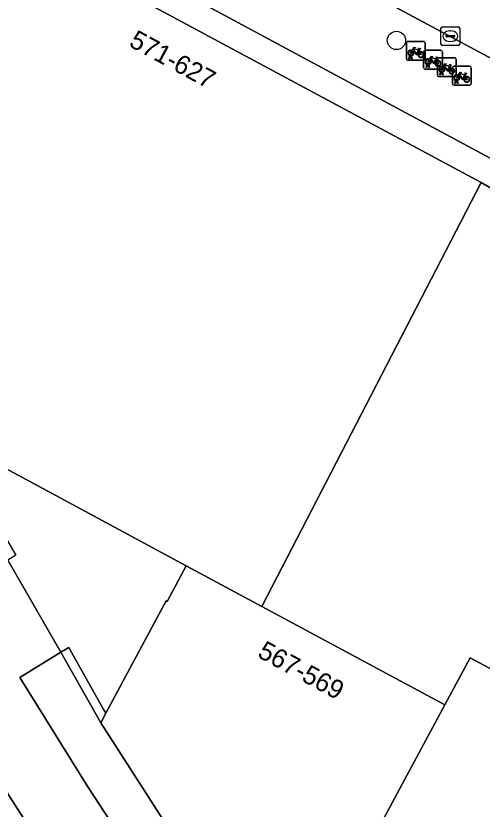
# Model space of a CAD drawing. Extents: x 159489 to 160304, y 383825 to 384531.
# Drawn here: x 159531.94 to 159556.82, y 384258.57 to 384300.92 of the extents above; entities that cross this region are included whole.
import ezdxf

# ---------------------------------------------------------------- set-up
doc = ezdxf.new("R2010")
doc.units = 0
for name, color, linetype in [('IMGEO_Boom', 7, 'Continuous'), ('IMGEO_Erf', 7, 'Continuous'), ('IMGEO_Fietsenrek', 7, 'Continuous'), ('IMGEO_Groenvoorziening', 7, 'Continuous'), ('IMGEO_Kolk', 7, 'Continuous'), ('IMGEO_Pand', 7, 'Continuous'), ('IMGEO_Pand_nummerreeks', 7, 'Continuous'), ('IMGEO_Rijbaan_lokaal_gesloten', 7, 'Continuous'), ('IMGEO_Voetpad_open', 7, 'Continuous')]:
    doc.layers.add(name, color=color, linetype=linetype)

msp = doc.modelspace()

# ---------------------------------------------------------------- linework, layer by layer
at = {"layer": 'IMGEO_Boom'}
msp.add_circle((159552.252, 384299.604), 0.489, dxfattribs=at)
at = {"layer": 'IMGEO_Erf'}
msp.add_lwpolyline([(159631.56, 384209.476), (159640.276, 384225.681), (159611.777, 384241.285), (159616.379, 384249.69), (159600.425, 384258.245), (159593.348, 384245.049), (159582.491, 384250.872), (159578.85, 384252.831), (159587.23, 384268.419), (159590.223, 384274), (159575.933, 384281.657), (159574.935, 384279.809), (159575.127, 384279.7), (159565.449, 384261.675), (159556.176, 384266.653), (159554.827, 384264.14), (159546.454, 384248.546), (159558.913, 384230.144), (159558.499, 384229.864), (159559.363, 384228.538), (159560.934, 384226.137), (159561.341, 384226.407), (159569.144, 384213.675)], dxfattribs=at)
msp.add_lwpolyline([(159541.03, 384271.564), (159528.221, 384278.456), (159531.931, 384272.12), (159531.499, 384271.869), (159534.333, 384266.954), (159534.768, 384267.2), (159536.603, 384263.927), (159536.735, 384263.691), (159539.953, 384269.688), (159540.015, 384269.655)], close=True, dxfattribs=at)
at = {"layer": 'IMGEO_Fietsenrek'}
for p, q in [((159552.854, 384299.547), (159553.695, 384299.547)), ((159553.695, 384299.547), (159552.854, 384299.547)), ((159552.779, 384298.622), (159552.779, 384299.463)), ((159552.779, 384299.463), (159552.779, 384298.622)), ((159553.466, 384299.096), (159553.502, 384299.001)), ((159553.777, 384299.077), (159554.618, 384299.077)), ((159554.618, 384299.077), (159553.777, 384299.077)), ((159553.779, 384299.472), (159553.779, 384298.631)), ((159553.779, 384298.631), (159553.779, 384299.472)), ((159552.906, 384298.631), (159552.945, 384298.791)), ((159552.975, 384298.779), (159552.94, 384298.631)), ((159553.017, 384298.803), (159553.016, 384298.807)), ((159553.058, 384298.631), (159553.024, 384298.773)), ((159553.048, 384298.814), (159553.049, 384298.807)), ((159553.056, 384298.777), (159553.091, 384298.631)), ((159553.702, 384298.152), (159553.702, 384298.993)), ((159553.702, 384298.993), (159553.702, 384298.152)), ((159554.508, 384298.677), (159555.349, 384298.677)), ((159555.349, 384298.677), (159554.508, 384298.677)), ((159554.702, 384299.002), (159554.702, 384298.161)), ((159554.702, 384298.161), (159554.702, 384299.002)), ((159553.704, 384298.547), (159552.863, 384298.547)), ((159552.863, 384298.547), (159553.704, 384298.547)), ((159552.94, 384298.631), (159552.906, 384298.631)), ((159553.091, 384298.631), (159553.058, 384298.631)), ((159553.829, 384298.161), (159553.868, 384298.321)), ((159553.898, 384298.309), (159553.863, 384298.161)), ((159553.94, 384298.333), (159553.939, 384298.337)), ((159553.981, 384298.161), (159553.947, 384298.303)), ((159553.971, 384298.344), (159553.972, 384298.337)), ((159553.979, 384298.307), (159554.014, 384298.161)), ((159554.389, 384298.626), (159554.425, 384298.531)), ((159554.433, 384297.752), (159554.433, 384298.593)), ((159554.433, 384298.593), (159554.433, 384297.752)), ((159555.12, 384298.226), (159555.156, 384298.131)), ((159555.309, 384298.224), (159556.15, 384298.224)), ((159556.15, 384298.224), (159555.309, 384298.224)), ((159555.433, 384298.602), (159555.433, 384297.761)), ((159555.433, 384297.761), (159555.433, 384298.602)), ((159554.627, 384298.077), (159553.786, 384298.077)), ((159553.786, 384298.077), (159554.627, 384298.077)), ((159553.863, 384298.161), (159553.829, 384298.161)), ((159554.014, 384298.161), (159553.981, 384298.161)), ((159554.56, 384297.761), (159554.599, 384297.921)), ((159554.629, 384297.909), (159554.594, 384297.761)), ((159554.671, 384297.933), (159554.67, 384297.937)), ((159554.712, 384297.761), (159554.678, 384297.903)), ((159554.702, 384297.944), (159554.703, 384297.937)), ((159554.71, 384297.907), (159554.745, 384297.761)), ((159555.234, 384297.299), (159555.234, 384298.14)), ((159555.234, 384298.14), (159555.234, 384297.299)), ((159556.234, 384298.149), (159556.234, 384297.308)), ((159556.234, 384297.308), (159556.234, 384298.149)), ((159555.358, 384297.677), (159554.517, 384297.677)), ((159554.517, 384297.677), (159555.358, 384297.677)), ((159554.594, 384297.761), (159554.56, 384297.761)), ((159554.745, 384297.761), (159554.712, 384297.761)), ((159555.361, 384297.308), (159555.4, 384297.468)), ((159555.43, 384297.456), (159555.395, 384297.308)), ((159555.472, 384297.48), (159555.471, 384297.484)), ((159555.513, 384297.308), (159555.479, 384297.45)), ((159555.503, 384297.491), (159555.504, 384297.484)), ((159555.511, 384297.454), (159555.546, 384297.308)), ((159555.921, 384297.773), (159555.957, 384297.678)), ((159556.159, 384297.224), (159555.318, 384297.224)), ((159555.318, 384297.224), (159556.159, 384297.224)), ((159555.395, 384297.308), (159555.361, 384297.308)), ((159555.546, 384297.308), (159555.513, 384297.308))]:
    msp.add_line(p, q, dxfattribs=at)
for points in [[(159553.092, 384299.073), (159553.187, 384299.237), (159553.273, 384299.223), (159553.275, 384299.214), (159553.219, 384299.203), (159553.192, 384299.158), (159553.448, 384299.117)], [(159553.388, 384298.829), (159553.338, 384298.829), (159553.147, 384299.08), (159553.128, 384299.048)], [(159553.435, 384299.092), (159553.178, 384299.133), (159553.161, 384299.104), (159553.328, 384298.884), (159553.435, 384299.092)], [(159553.483, 384298.994), (159553.453, 384299.071), (159553.344, 384298.853), (159553.387, 384298.853)], [(159553.448, 384299.117), (159553.473, 384299.166), (159553.467, 384299.17), (159553.444, 384299.174), (159553.432, 384299.181), (159553.431, 384299.184), (159553.433, 384299.189), (159553.528, 384299.174), (159553.53, 384299.164), (159553.52, 384299.151), (159553.508, 384299.145), (159553.494, 384299.151), (159553.466, 384299.096)], [(159553.113, 384299.021), (159553.061, 384298.931), (159553.021, 384298.906), (159553.022, 384298.953), (159553.077, 384299.047)], [(159553.417, 384298.853), (159553.537, 384298.852), (159553.493, 384298.966)], [(159553.513, 384298.973), (159553.568, 384298.828), (159553.418, 384298.828)], [(159554.015, 384298.603), (159554.11, 384298.767), (159554.196, 384298.753), (159554.198, 384298.744), (159554.142, 384298.733), (159554.115, 384298.688), (159554.371, 384298.647)], [(159554.358, 384298.622), (159554.101, 384298.663), (159554.084, 384298.634), (159554.251, 384298.414), (159554.358, 384298.622)], [(159554.371, 384298.647), (159554.396, 384298.696), (159554.39, 384298.7), (159554.367, 384298.704), (159554.355, 384298.711), (159554.354, 384298.714), (159554.356, 384298.719), (159554.451, 384298.704), (159554.453, 384298.694), (159554.443, 384298.681), (159554.431, 384298.675), (159554.417, 384298.681), (159554.389, 384298.626)], [(159554.036, 384298.551), (159553.984, 384298.461), (159553.944, 384298.436), (159553.945, 384298.483), (159554, 384298.577)], [(159554.311, 384298.359), (159554.261, 384298.359), (159554.07, 384298.61), (159554.051, 384298.578)], [(159554.406, 384298.524), (159554.376, 384298.601), (159554.267, 384298.383), (159554.31, 384298.383)], [(159554.34, 384298.383), (159554.46, 384298.382), (159554.416, 384298.496)], [(159554.436, 384298.503), (159554.491, 384298.358), (159554.341, 384298.358)], [(159554.746, 384298.203), (159554.841, 384298.367), (159554.927, 384298.353), (159554.929, 384298.344), (159554.873, 384298.333), (159554.846, 384298.288), (159555.102, 384298.247)], [(159555.089, 384298.222), (159554.832, 384298.263), (159554.815, 384298.234), (159554.982, 384298.014), (159555.089, 384298.222)], [(159555.102, 384298.247), (159555.127, 384298.296), (159555.121, 384298.3), (159555.098, 384298.304), (159555.086, 384298.311), (159555.085, 384298.314), (159555.087, 384298.319), (159555.182, 384298.304), (159555.184, 384298.294), (159555.174, 384298.281), (159555.162, 384298.275), (159555.148, 384298.281), (159555.12, 384298.226)], [(159554.767, 384298.151), (159554.715, 384298.061), (159554.675, 384298.036), (159554.676, 384298.083), (159554.731, 384298.177)], [(159555.042, 384297.959), (159554.992, 384297.959), (159554.801, 384298.21), (159554.782, 384298.178)], [(159555.137, 384298.124), (159555.107, 384298.201), (159554.998, 384297.983), (159555.041, 384297.983)], [(159555.071, 384297.983), (159555.191, 384297.982), (159555.147, 384298.096)], [(159555.167, 384298.103), (159555.222, 384297.958), (159555.072, 384297.958)], [(159555.547, 384297.75), (159555.642, 384297.914), (159555.728, 384297.9), (159555.73, 384297.891), (159555.674, 384297.88), (159555.647, 384297.835), (159555.903, 384297.794)], [(159555.89, 384297.769), (159555.633, 384297.81), (159555.616, 384297.781), (159555.783, 384297.561), (159555.89, 384297.769)], [(159555.903, 384297.794), (159555.928, 384297.843), (159555.922, 384297.847), (159555.899, 384297.851), (159555.887, 384297.858), (159555.886, 384297.861), (159555.888, 384297.866), (159555.983, 384297.851), (159555.985, 384297.841), (159555.975, 384297.828), (159555.963, 384297.822), (159555.949, 384297.828), (159555.921, 384297.773)], [(159555.568, 384297.698), (159555.516, 384297.608), (159555.476, 384297.583), (159555.477, 384297.63), (159555.532, 384297.724)], [(159555.843, 384297.506), (159555.793, 384297.506), (159555.602, 384297.757), (159555.583, 384297.725)], [(159555.938, 384297.671), (159555.908, 384297.748), (159555.799, 384297.53), (159555.842, 384297.53)], [(159555.872, 384297.53), (159555.992, 384297.529), (159555.948, 384297.643)], [(159555.968, 384297.65), (159556.023, 384297.505), (159555.873, 384297.505)]]:
    msp.add_lwpolyline(points, dxfattribs=at)
for centre, radius, start, end in [((159552.857, 384299.469), 0.0779, 92.4484, 184.2845), ((159552.857, 384299.469), 0.0779, 92.4484, 184.2845), ((159553.701, 384299.469), 0.0779, 2.4484, 94.2845), ((159553.701, 384299.469), 0.0779, 2.4484, 94.2845), ((159553.019, 384298.932), 0.159, 62.6766, 242.1369), ((159553.019, 384298.932), 0.129, 63.3192, 238.903), ((159553.78, 384298.999), 0.0779, 92.4484, 184.2845), ((159553.78, 384298.999), 0.0779, 92.4484, 184.2845), ((159554.624, 384298.999), 0.0779, 2.4484, 94.2845), ((159554.624, 384298.999), 0.0779, 2.4484, 94.2845), ((159552.999, 384298.803), 0.0499, 12.8025, 158.6934), ((159553.019, 384298.932), 0.159, 253.9967, 271.7867), ((159552.999, 384298.803), 0.0174, 12.8025, 163.4502), ((159553.019, 384298.932), 0.129, 253.415, 269.0204), ((159553.019, 384298.932), 0.129, 283.6043, 43.4302), ((159553.019, 384298.932), 0.159, 283.5766, 46.6042), ((159553.546, 384298.848), 0.159, 113.3408, 178.3217), ((159553.546, 384298.848), 0.159, 187.0065, 105.7708), ((159553.546, 384298.848), 0.129, 113.923, 177.9556), ((159553.546, 384298.848), 0.129, 188.6715, 104.5883), ((159554.511, 384298.599), 0.0779, 92.4484, 184.2845), ((159554.511, 384298.599), 0.0779, 92.4484, 184.2845), ((159555.355, 384298.599), 0.0779, 2.4484, 94.2845), ((159555.355, 384298.599), 0.0779, 2.4484, 94.2845), ((159552.857, 384298.625), 0.0779, 182.4484, 274.2845), ((159552.857, 384298.625), 0.0779, 182.4484, 274.2845), ((159553.701, 384298.625), 0.0779, 272.4484, 4.2845), ((159553.701, 384298.625), 0.0779, 272.4484, 4.2845), ((159553.942, 384298.462), 0.159, 62.6766, 242.1369), ((159553.942, 384298.462), 0.129, 63.3192, 238.903), ((159553.922, 384298.333), 0.0499, 12.8025, 158.6934), ((159553.942, 384298.462), 0.159, 253.9967, 271.7867), ((159553.922, 384298.333), 0.0174, 12.8025, 163.4502), ((159553.942, 384298.462), 0.129, 253.415, 269.0204), ((159553.942, 384298.462), 0.129, 283.6043, 43.4302), ((159553.942, 384298.462), 0.159, 283.5766, 46.6042), ((159554.469, 384298.378), 0.159, 113.3408, 178.3217), ((159554.469, 384298.378), 0.159, 187.0065, 105.7708), ((159554.469, 384298.378), 0.129, 113.923, 177.9556), ((159554.469, 384298.378), 0.129, 188.6715, 104.5883), ((159554.673, 384298.062), 0.159, 62.6766, 242.1369), ((159555.312, 384298.146), 0.0779, 92.4484, 184.2845), ((159555.312, 384298.146), 0.0779, 92.4484, 184.2845), ((159556.156, 384298.146), 0.0779, 2.4484, 94.2845), ((159556.156, 384298.146), 0.0779, 2.4484, 94.2845), ((159553.78, 384298.155), 0.0779, 182.4484, 274.2845), ((159553.78, 384298.155), 0.0779, 182.4484, 274.2845), ((159554.673, 384298.062), 0.129, 63.3192, 238.903), ((159554.653, 384297.933), 0.0499, 12.8025, 158.6934), ((159554.624, 384298.155), 0.0779, 272.4484, 4.2845), ((159554.624, 384298.155), 0.0779, 272.4484, 4.2845), ((159554.673, 384298.062), 0.159, 253.9967, 271.7867), ((159554.653, 384297.933), 0.0174, 12.8025, 163.4502), ((159554.673, 384298.062), 0.129, 253.415, 269.0204), ((159554.673, 384298.062), 0.129, 283.6043, 43.4302), ((159554.673, 384298.062), 0.159, 283.5766, 46.6042), ((159555.2, 384297.978), 0.159, 113.3408, 178.3217), ((159555.2, 384297.978), 0.159, 187.0065, 105.7708), ((159555.2, 384297.978), 0.129, 113.923, 177.9556), ((159555.2, 384297.978), 0.129, 188.6715, 104.5883), ((159554.511, 384297.755), 0.0779, 182.4484, 274.2845), ((159554.511, 384297.755), 0.0779, 182.4484, 274.2845), ((159555.474, 384297.609), 0.159, 62.6766, 242.1369), ((159555.474, 384297.609), 0.129, 63.3192, 238.903), ((159555.355, 384297.755), 0.0779, 272.4484, 4.2845), ((159555.355, 384297.755), 0.0779, 272.4484, 4.2845), ((159555.454, 384297.48), 0.0499, 12.8025, 158.6934), ((159555.474, 384297.609), 0.159, 253.9967, 271.7867), ((159555.454, 384297.48), 0.0174, 12.8025, 163.4502), ((159555.474, 384297.609), 0.129, 253.415, 269.0204), ((159555.474, 384297.609), 0.129, 283.6043, 43.4302), ((159555.474, 384297.609), 0.159, 283.5766, 46.6042), ((159556.001, 384297.525), 0.159, 113.3408, 178.3217), ((159556.001, 384297.525), 0.159, 187.0065, 105.7708), ((159556.001, 384297.525), 0.129, 113.923, 177.9556), ((159556.001, 384297.525), 0.129, 188.6715, 104.5883), ((159555.312, 384297.302), 0.0779, 182.4484, 274.2845), ((159555.312, 384297.302), 0.0779, 182.4484, 274.2845), ((159556.156, 384297.302), 0.0779, 272.4484, 4.2845), ((159556.156, 384297.302), 0.0779, 272.4484, 4.2845)]:
    msp.add_arc(centre, radius, start, end, dxfattribs=at)
at = {"layer": 'IMGEO_Groenvoorziening'}
for points in [[(159546.189, 384248.053), (159536.462, 384263.182), (159534.333, 384266.954), (159532.141, 384265.589), (159535.783, 384259.763), (159537.922, 384256.46), (159543.06, 384248.654), (159556.437, 384228.499), (159558.499, 384229.864)], [(159534.333, 384266.954), (159536.462, 384263.182), (159536.735, 384263.691), (159536.603, 384263.927), (159534.768, 384267.2)], [(159531.17, 384259.924), (159529.475, 384258.882), (159530.676, 384256.993), (159531.995, 384254.871), (159533.67, 384255.984), (159532.339, 384258.083)]]:
    msp.add_lwpolyline(points, close=True, dxfattribs=at)
at = {"layer": 'IMGEO_Kolk'}
for p, q in [((159554.701, 384300.333), (159555.553, 384300.333)), ((159554.626, 384299.407), (159554.626, 384300.259)), ((159555.114, 384300.113), (159555.139, 384300.113)), ((159555.627, 384300.259), (159555.627, 384299.407)), ((159554.885, 384299.827), (159554.885, 384299.839)), ((159555.323, 384299.79), (159554.925, 384299.79)), ((159554.928, 384299.876), (159555.326, 384299.876)), ((159555.137, 384299.553), (159555.112, 384299.553)), ((159555.369, 384299.839), (159555.369, 384299.827)), ((159555.553, 384299.333), (159554.701, 384299.333))]:
    msp.add_line(p, q, dxfattribs=at)
for points in [[(159554.701, 384300.333), (159555.553, 384300.333)], [(159554.626, 384299.407), (159554.626, 384300.259)], [(159555.627, 384300.259), (159555.627, 384299.407)], [(159555.553, 384299.333), (159554.701, 384299.333)]]:
    msp.add_lwpolyline(points, dxfattribs=at)
for centre, radius, start, end in [((159554.703, 384300.257), 0.0765, 91.552, 178.448), ((159554.703, 384300.257), 0.0765, 91.552, 178.448), ((159555.551, 384300.257), 0.0765, 1.552, 88.448), ((159555.551, 384300.257), 0.0765, 1.552, 88.448), ((159554.925, 384299.836), 0.0403, 85.8775, 175.7526), ((159554.922, 384299.826), 0.0366, 178.938, 274.7102), ((159555.326, 384299.833), 0.043, 264.8664, 352.4533), ((159555.33, 384299.838), 0.0386, 1.7309, 96.639), ((159554.703, 384299.409), 0.0765, 181.552, 268.448), ((159554.703, 384299.409), 0.0765, 181.552, 268.448), ((159555.551, 384299.409), 0.0765, 271.552, 358.448), ((159555.551, 384299.409), 0.0765, 271.552, 358.448)]:
    msp.add_arc(centre, radius, start, end, dxfattribs=at)
for centre, major_axis, ratio, start_param, end_param in [((159555.113, 384299.833), (-0.387, 0.002), 0.722429, 4.712389, 7.853982), ((159555.138, 384299.833), (-0.39, 0.002), 0.717154, 1.570796, 4.712389)]:
    msp.add_ellipse(centre, major_axis=major_axis, ratio=ratio, start_param=start_param, end_param=end_param, dxfattribs=at)
at = {"layer": 'IMGEO_Pand'}
for points in [[(159556.766, 384292.015), (159527.484, 384307.756), (159519.695, 384293.297), (159519.377, 384292.707), (159522.438, 384287.447), (159523.926, 384284.889), (159527.419, 384278.887), (159528.221, 384278.456), (159541.03, 384271.564), (159545.068, 384269.391)], [(159575.127, 384279.7), (159574.935, 384279.809), (159575.933, 384281.657), (159563.611, 384288.299), (159557.204, 384291.777), (159556.766, 384292.015), (159545.068, 384269.391), (159554.827, 384264.14), (159556.176, 384266.653), (159565.449, 384261.675)], [(159554.827, 384264.14), (159545.068, 384269.391), (159541.03, 384271.564), (159540.015, 384269.655), (159539.953, 384269.688), (159536.735, 384263.691), (159536.462, 384263.182), (159546.189, 384248.053), (159546.454, 384248.546)]]:
    msp.add_lwpolyline(points, close=True, dxfattribs=at)
at = {"layer": 'IMGEO_Rijbaan_lokaal_gesloten'}
msp.add_lwpolyline([(159524.477, 384316.223), (159526.867, 384315.023), (159527.963, 384314.433), (159535.565, 384310.345), (159536.44, 384311.971), (159549.851, 384304.759), (159550.324, 384304.504), (159549.449, 384302.878), (159558.914, 384297.788), (159559.789, 384299.414), (159596.815, 384279.502), (159606.884, 384274.087), (159606.009, 384272.461), (159610.125, 384270.247), (159610.999, 384271.873), (159634.42, 384259.278), (159633.545, 384257.652), (159643.266, 384252.424), (159644.14, 384254.05), (159648.99, 384251.442), (159648.115, 384249.816), (159649.108, 384249.282), (159652.612, 384247.398)], dxfattribs=at)
at = {"layer": 'IMGEO_Voetpad_open'}
for points in [[(159652.612, 384247.398), (159649.108, 384249.282), (159648.115, 384249.816), (159643.266, 384252.424), (159633.545, 384257.652), (159610.125, 384270.247), (159606.009, 384272.461), (159595.94, 384277.876), (159558.914, 384297.788), (159549.449, 384302.878), (159535.565, 384310.345), (159527.963, 384314.433)], [(159514.758, 384298.232), (159516.4, 384294.599), (159517.502, 384296.664), (159524.97, 384310.657), (159525.855, 384310.207), (159526.055, 384310.099), (159576.611, 384282.913), (159575.933, 384281.657), (159590.223, 384274), (159620.712, 384257.605), (159621.017, 384257.441), (159621.346, 384257.26), (159646.05, 384243.709), (159649.079, 384242.048), (159654.684, 384240.484)], [(159543.06, 384248.654), (159537.922, 384256.46), (159535.783, 384259.763), (159532.141, 384265.589), (159534.333, 384266.954), (159531.499, 384271.869), (159529.156, 384270.537), (159524.479, 384278.85), (159521.885, 384283.676), (159520.528, 384286.319), (159516.4, 384294.599), (159514.758, 384298.232)], [(159527.795, 384263.144), (159527.066, 384262.703), (159527.297, 384262.272), (159527.408, 384262.135), (159529.056, 384263.238), (159530.14, 384261.558), (159531.17, 384259.924), (159532.339, 384258.083), (159533.67, 384255.984), (159534.768, 384254.316), (159538.106, 384249.307), (159539.805, 384246.756), (159538.058, 384245.622), (159539.105, 384244.038), (159540.836, 384245.167), (159541.101, 384245.34), (159546.045, 384237.884), (159553.341, 384226.923), (159558.212, 384219.486), (159567.124, 384205.873)]]:
    msp.add_lwpolyline(points, dxfattribs=at)
msp.add_lwpolyline([(159526.055, 384310.099), (159525.406, 384308.865), (159527.484, 384307.756), (159556.766, 384292.015), (159557.204, 384291.777), (159563.611, 384288.299), (159575.933, 384281.657), (159576.611, 384282.913)], close=True, dxfattribs=at)

# ---------------------------------------------------------------- texts
at = {"layer": 'IMGEO_Pand_nummerreeks'}
for s, rotation, p in [('571-627', 331.5412, (159537.916, 384299.323)), ('567-569', 331.5183, (159544.78, 384266.72))]:
    msp.add_text(s, height=1, rotation=rotation, dxfattribs=at).set_placement(p)

doc.saveas('drawing.dxf')
